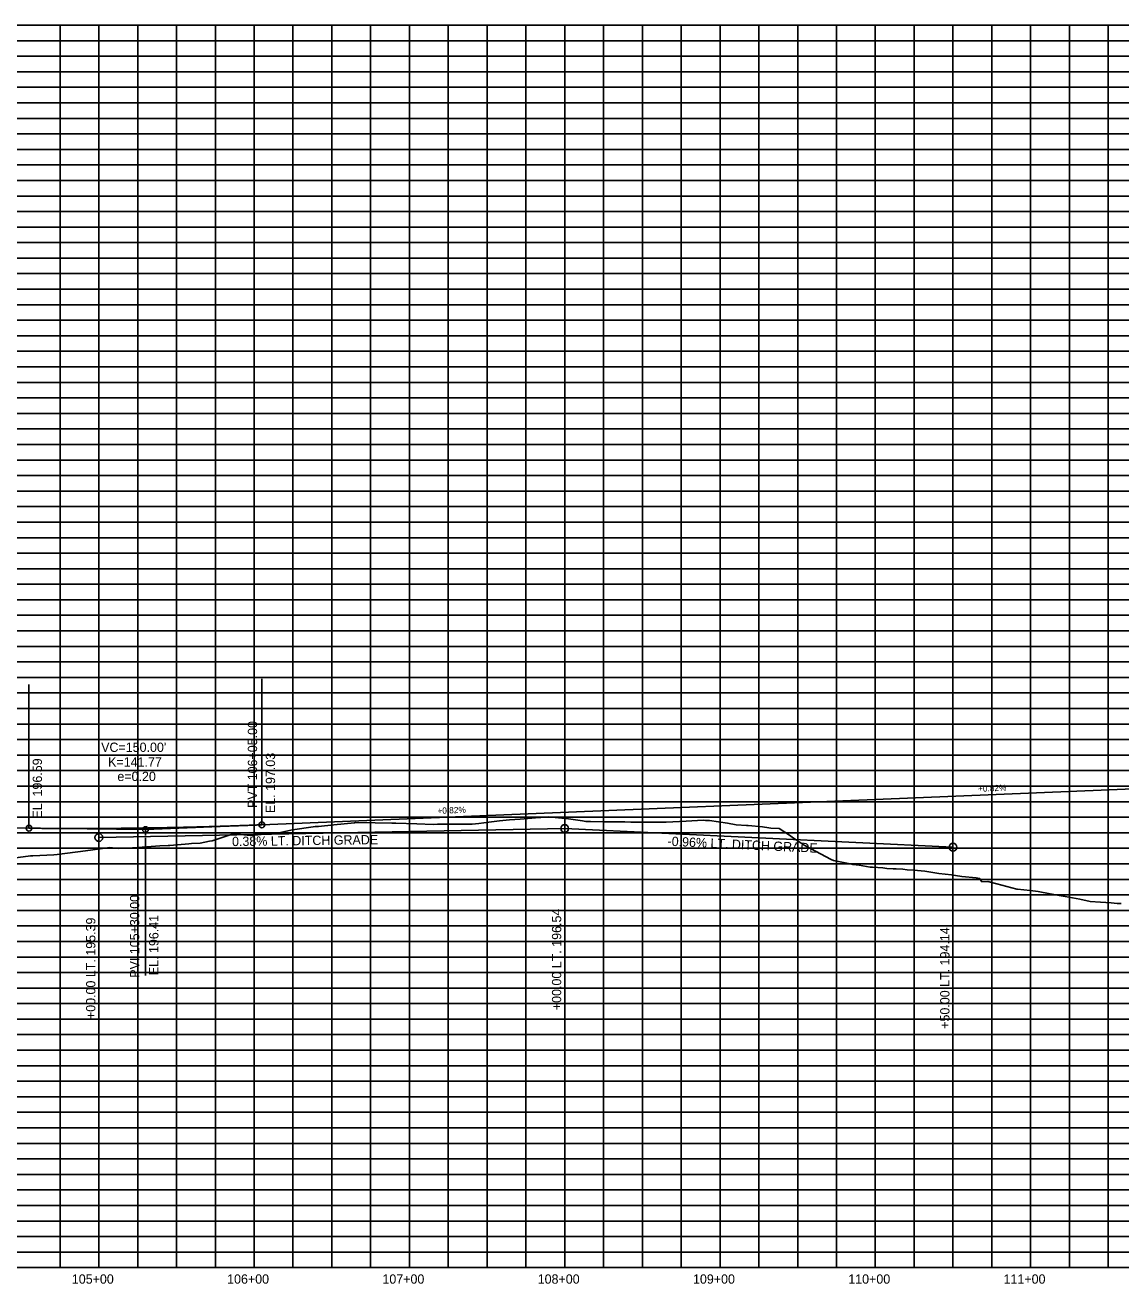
# Model space of a CAD drawing. Extents: x 1384498 to 1391279, y 1965973 to 1976560.
# Drawn here: x 1388901 to 1389607, y 1975299 to 1976110 of the extents above; entities that cross this region are included whole.
import ezdxf

# ---------------------------------------------------------------- set-up
doc = ezdxf.new("R2010")
doc.units = 0
for name, color, linetype in [('Default', 7, 'Continuous'), ('R_Axis_Annotation', 7, 'Continuous'), ('R_Exist Surface', 7, 'Continuous'), ('R_Grid', 7, 'Continuous'), ('R_Grid_Minor', 7, 'Continuous'), ('R_Vert Alg', 7, 'Continuous'), ('R_Vert Alg Annot', 7, 'Continuous')]:
    doc.layers.add(name, color=color, linetype=linetype)

msp = doc.modelspace()

# ---------------------------------------------------------------- linework, layer by layer
at = {"layer": 'Default'}
msp.add_line((1388248.79, 1975309.84), (1390648.79, 1975309.84), dxfattribs=at)
at = {"layer": 'R_Exist Surface'}
for points in [[(1388955.91, 1975580.31), (1388961.26, 1975579.63), (1388970.41, 1975580.09), (1388979.6, 1975580.85), (1388987.97, 1975581.33), (1388993.32, 1975581.64), (1388994.43, 1975581.7), (1389006.66, 1975582.79), (1389008.42, 1975582.92), (1389014, 1975583.18), (1389020, 1975584.4), (1389021.8, 1975584.74), (1389033.35, 1975588.48), (1389035.45, 1975589.12), (1389039.97, 1975588.7), (1389046.35, 1975588.11), (1389046.69, 1975588.15), (1389060.03, 1975589.34), (1389062.84, 1975589.5), (1389064.17, 1975589.74), (1389064.69, 1975589.83), (1389072.45, 1975591.51), (1389073.38, 1975591.65), (1389086.72, 1975593.6), (1389088.08, 1975593.8), (1389089.06, 1975593.83), (1389090.22, 1975593.89), (1389100.06, 1975594.93), (1389113.41, 1975596.34), (1389114.06, 1975596.41), (1389126.75, 1975596.22), (1389137.41, 1975596.06), (1389139.07, 1975596.04), (1389139.19, 1975596.04), (1389140.1, 1975596.01), (1389153.44, 1975595.55), (1389164.11, 1975595.21), (1389166.78, 1975595.28), (1389168.8, 1975595.33), (1389180.13, 1975595.35), (1389189.2, 1975595.39), (1389193.47, 1975595.9), (1389199.97, 1975596.7), (1389206.81, 1975597.43), (1389213.31, 1975598.15), (1389220.16, 1975598.64), (1389232.59, 1975599.57), (1389233.5, 1975599.67), (1389238.35, 1975600.18), (1389246.84, 1975599.25), (1389251.31, 1975598.78), (1389260.19, 1975597.47), (1389262.31, 1975597.15), (1389263.71, 1975597.08), (1389265.3, 1975597), (1389273.53, 1975596.98), (1389286.87, 1975596.91), (1389287.54, 1975596.9), (1389291.37, 1975596.67), (1389299.23, 1975596.61), (1389300.22, 1975596.62), (1389313.56, 1975596.63), (1389314, 1975596.63), (1389326.9, 1975597.32), (1389337.84, 1975597.87), (1389339.51, 1975597.8), (1389340.23, 1975597.83), (1389340.25, 1975597.83), (1389342.11, 1975597.71), (1389353.59, 1975595.94), (1389359.13, 1975595.03), (1389365.77, 1975594.57), (1389366.93, 1975594.47), (1389376.09, 1975593.6), (1389380.28, 1975592.99), (1389381.52, 1975592.81), (1389386.93, 1975592.54), (1389393.62, 1975588.2), (1389395.26, 1975587.07), (1389402.99, 1975581.76), (1389406.96, 1975579.8), (1389420.31, 1975572.73), (1389421.79, 1975571.89), (1389422.77, 1975571.78), (1389423.04, 1975571.74), (1389433.65, 1975569.59), (1389434.38, 1975569.43), (1389438.49, 1975569.04), (1389445.51, 1975567.77), (1389446.99, 1975567.68), (1389453.57, 1975567.23), (1389456.16, 1975566.83), (1389460.34, 1975566.71), (1389462.13, 1975566.65), (1389466.48, 1975566.37), (1389469.32, 1975566.05), (1389473.68, 1975565.68), (1389480.68, 1975565.05), (1389487.02, 1975564.08), (1389489.75, 1975563.65), (1389497.8, 1975562.76)], [(1388893.7, 1975573.41), (1388904.83, 1975574.88), (1388906.11, 1975574.95), (1388906.32, 1975574.96), (1388919.68, 1975575.65), (1388921.92, 1975575.74), (1388940.08, 1975578.19), (1388955.91, 1975580.31)], [(1389497.8, 1975562.76), (1389500.37, 1975562.37), (1389504.45, 1975561.73), (1389513.71, 1975560.72), (1389515.94, 1975560.47), (1389517.48, 1975558.19), (1389521.14, 1975558.41), (1389527.05, 1975556.89), (1389539.94, 1975553.56), (1389540.4, 1975553.52), (1389548.58, 1975552.65), (1389553.74, 1975551.94), (1389555.79, 1975551.65), (1389567.08, 1975549.54), (1389571.11, 1975548.76), (1389580.43, 1975546.98), (1389587.19, 1975545.65), (1389593.77, 1975545.16), (1389600.66, 1975544.63), (1389604.55, 1975544.36), (1389607.11, 1975544.19)]]:
    msp.add_lwpolyline(points, dxfattribs=at)
at = {"layer": 'R_Grid'}
for p, q in [((1388248.79, 1976109.84), (1391048.79, 1976109.84)), ((1388248.79, 1976109.84), (1391048.79, 1976109.84)), ((1388948.79, 1975309.84), (1388948.79, 1976109.84)), ((1389048.79, 1975309.84), (1389048.79, 1976109.84)), ((1389148.79, 1975309.84), (1389148.79, 1976109.84)), ((1389248.79, 1975309.84), (1389248.79, 1976109.84)), ((1389348.79, 1975309.84), (1389348.79, 1976109.84)), ((1389448.79, 1975309.84), (1389448.79, 1976109.84)), ((1389548.79, 1975309.84), (1389548.79, 1976109.84)), ((1388248.79, 1976059.84), (1391048.79, 1976059.84)), ((1388248.79, 1976009.84), (1391048.79, 1976009.84)), ((1388248.79, 1975959.84), (1391048.79, 1975959.84)), ((1388248.79, 1975909.84), (1391048.79, 1975909.84)), ((1388248.79, 1975859.84), (1391048.79, 1975859.84)), ((1388248.79, 1975809.84), (1391048.79, 1975809.84)), ((1388248.79, 1975759.84), (1391048.79, 1975759.84)), ((1388248.79, 1975709.84), (1391048.79, 1975709.84)), ((1388248.79, 1975659.84), (1391048.79, 1975659.84)), ((1388248.79, 1975609.84), (1391048.79, 1975609.84)), ((1388248.79, 1975559.84), (1391048.79, 1975559.84)), ((1388248.79, 1975509.84), (1391048.79, 1975509.84)), ((1388248.79, 1975459.84), (1391048.79, 1975459.84)), ((1388248.79, 1975409.84), (1391048.79, 1975409.84)), ((1388248.79, 1975359.84), (1391048.79, 1975359.84)), ((1388248.79, 1975309.84), (1391048.79, 1975309.84))]:
    msp.add_line(p, q, dxfattribs=at)
at = {"layer": 'R_Grid_Minor'}
for p, q in [((1388923.79, 1975309.84), (1388923.79, 1976109.84)), ((1388973.79, 1975309.84), (1388973.79, 1976109.84)), ((1388998.79, 1975309.84), (1388998.79, 1976109.84)), ((1389023.79, 1975309.84), (1389023.79, 1976109.84)), ((1389073.79, 1975309.84), (1389073.79, 1976109.84)), ((1389098.79, 1975309.84), (1389098.79, 1976109.84)), ((1389123.79, 1975309.84), (1389123.79, 1976109.84)), ((1389173.79, 1975309.84), (1389173.79, 1976109.84)), ((1389198.79, 1975309.84), (1389198.79, 1976109.84)), ((1389223.79, 1975309.84), (1389223.79, 1976109.84)), ((1389273.79, 1975309.84), (1389273.79, 1976109.84)), ((1389298.79, 1975309.84), (1389298.79, 1976109.84)), ((1389323.79, 1975309.84), (1389323.79, 1976109.84)), ((1389373.79, 1975309.84), (1389373.79, 1976109.84)), ((1389398.79, 1975309.84), (1389398.79, 1976109.84)), ((1389423.79, 1975309.84), (1389423.79, 1976109.84)), ((1389473.79, 1975309.84), (1389473.79, 1976109.84)), ((1389498.79, 1975309.84), (1389498.79, 1976109.84)), ((1389523.79, 1975309.84), (1389523.79, 1976109.84)), ((1389573.79, 1975309.84), (1389573.79, 1976109.84)), ((1389598.79, 1975309.84), (1389598.79, 1976109.84)), ((1388248.79, 1976099.84), (1391048.79, 1976099.84)), ((1388248.79, 1976089.84), (1391048.79, 1976089.84)), ((1388248.79, 1976079.84), (1391048.79, 1976079.84)), ((1388248.79, 1976069.84), (1391048.79, 1976069.84)), ((1388248.79, 1976049.84), (1391048.79, 1976049.84)), ((1388248.79, 1976039.84), (1391048.79, 1976039.84)), ((1388248.79, 1976029.84), (1391048.79, 1976029.84)), ((1388248.79, 1976019.84), (1391048.79, 1976019.84)), ((1388248.79, 1975999.84), (1391048.79, 1975999.84)), ((1388248.79, 1975989.84), (1391048.79, 1975989.84)), ((1388248.79, 1975979.84), (1391048.79, 1975979.84)), ((1388248.79, 1975969.84), (1391048.79, 1975969.84)), ((1388248.79, 1975949.84), (1391048.79, 1975949.84)), ((1388248.79, 1975939.84), (1391048.79, 1975939.84)), ((1388248.79, 1975929.84), (1391048.79, 1975929.84)), ((1388248.79, 1975919.84), (1391048.79, 1975919.84)), ((1388248.79, 1975899.84), (1391048.79, 1975899.84)), ((1388248.79, 1975889.84), (1391048.79, 1975889.84)), ((1388248.79, 1975879.84), (1391048.79, 1975879.84)), ((1388248.79, 1975869.84), (1391048.79, 1975869.84)), ((1388248.79, 1975849.84), (1391048.79, 1975849.84)), ((1388248.79, 1975839.84), (1391048.79, 1975839.84)), ((1388248.79, 1975829.84), (1391048.79, 1975829.84)), ((1388248.79, 1975819.84), (1391048.79, 1975819.84)), ((1388248.79, 1975799.84), (1391048.79, 1975799.84)), ((1388248.79, 1975789.84), (1391048.79, 1975789.84)), ((1388248.79, 1975779.84), (1391048.79, 1975779.84)), ((1388248.79, 1975769.84), (1391048.79, 1975769.84)), ((1388248.79, 1975749.84), (1391048.79, 1975749.84)), ((1388248.79, 1975739.84), (1391048.79, 1975739.84)), ((1388248.79, 1975729.84), (1391048.79, 1975729.84)), ((1388248.79, 1975719.84), (1391048.79, 1975719.84)), ((1388248.79, 1975699.84), (1391048.79, 1975699.84)), ((1388248.79, 1975689.84), (1391048.79, 1975689.84)), ((1388248.79, 1975679.84), (1391048.79, 1975679.84)), ((1388248.79, 1975669.84), (1391048.79, 1975669.84)), ((1388248.79, 1975649.84), (1391048.79, 1975649.84)), ((1388248.79, 1975639.84), (1391048.79, 1975639.84)), ((1388248.79, 1975629.84), (1391048.79, 1975629.84)), ((1388248.79, 1975619.84), (1391048.79, 1975619.84)), ((1388248.79, 1975599.84), (1391048.79, 1975599.84)), ((1388248.79, 1975589.84), (1391048.79, 1975589.84)), ((1388248.79, 1975579.84), (1391048.79, 1975579.84)), ((1388248.79, 1975569.84), (1391048.79, 1975569.84)), ((1388248.79, 1975549.84), (1391048.79, 1975549.84)), ((1388248.79, 1975539.84), (1391048.79, 1975539.84)), ((1388248.79, 1975529.84), (1391048.79, 1975529.84)), ((1388248.79, 1975519.84), (1391048.79, 1975519.84)), ((1388248.79, 1975499.84), (1391048.79, 1975499.84)), ((1388248.79, 1975489.84), (1391048.79, 1975489.84)), ((1388248.79, 1975479.84), (1391048.79, 1975479.84)), ((1388248.79, 1975469.84), (1391048.79, 1975469.84)), ((1388248.79, 1975449.84), (1391048.79, 1975449.84)), ((1388248.79, 1975439.84), (1391048.79, 1975439.84)), ((1388248.79, 1975429.84), (1391048.79, 1975429.84)), ((1388248.79, 1975419.84), (1391048.79, 1975419.84)), ((1388248.79, 1975399.84), (1391048.79, 1975399.84)), ((1388248.79, 1975389.84), (1391048.79, 1975389.84)), ((1388248.79, 1975379.84), (1391048.79, 1975379.84)), ((1388248.79, 1975369.84), (1391048.79, 1975369.84)), ((1388248.79, 1975349.84), (1391048.79, 1975349.84)), ((1388248.79, 1975339.84), (1391048.79, 1975339.84)), ((1388248.79, 1975329.84), (1391048.79, 1975329.84)), ((1388248.79, 1975319.84), (1391048.79, 1975319.84))]:
    msp.add_line(p, q, dxfattribs=at)
at = {"layer": 'R_Vert Alg'}
for p, q in [((1389053.79, 1975594.97), (1389634.53, 1975618.83)), ((1388748.79, 1975594.61), (1388903.79, 1975592.77)), ((1389248.79, 1975592.54), (1388948.79, 1975586.79)), ((1389248.79, 1975592.54), (1389498.79, 1975580.54))]:
    msp.add_line(p, q, dxfattribs=at)
msp.add_spline([(1388903.79, 1975592.77), (1388906.79, 1975592.74), (1388909.79, 1975592.71), (1388912.79, 1975592.68), (1388915.79, 1975592.66), (1388918.79, 1975592.64), (1388921.79, 1975592.62), (1388924.79, 1975592.6), (1388927.79, 1975592.59), (1388930.79, 1975592.58), (1388933.79, 1975592.58), (1388936.79, 1975592.58), (1388939.79, 1975592.58), (1388942.79, 1975592.58), (1388945.79, 1975592.59), (1388948.79, 1975592.6), (1388951.79, 1975592.61), (1388954.79, 1975592.63), (1388957.79, 1975592.65), (1388960.79, 1975592.67), (1388963.79, 1975592.7), (1388966.79, 1975592.73), (1388969.79, 1975592.76), (1388972.79, 1975592.8), (1388975.79, 1975592.84), (1388978.79, 1975592.88), (1388981.79, 1975592.93), (1388984.79, 1975592.97), (1388987.79, 1975593.03), (1388990.79, 1975593.08), (1388993.79, 1975593.14), (1388996.79, 1975593.2), (1388999.79, 1975593.27), (1389002.79, 1975593.33), (1389005.79, 1975593.4), (1389008.79, 1975593.48), (1389011.79, 1975593.56), (1389014.79, 1975593.64), (1389017.79, 1975593.72), (1389020.79, 1975593.81), (1389023.79, 1975593.9), (1389026.79, 1975593.99), (1389029.79, 1975594.09), (1389032.79, 1975594.18), (1389035.79, 1975594.29), (1389038.79, 1975594.39), (1389041.79, 1975594.5), (1389044.79, 1975594.61), (1389047.79, 1975594.73), (1389050.79, 1975594.85), (1389053.79, 1975594.97)], degree=3, dxfattribs=at)
at = {"layer": 'R_Vert Alg Annot'}
for p, q in [((1389053.78, 1975604.97), (1389053.78, 1975688.97)), ((1388903.78, 1975601.33), (1388903.78, 1975685.33)), ((1388903.79, 1975592.77), (1388903.79, 1975602.77)), ((1389053.78, 1975594.97), (1389053.78, 1975604.97)), ((1388903.79, 1975592.77), (1388978.78, 1975591.89)), ((1389053.78, 1975594.97), (1388978.78, 1975591.89)), ((1388978.78, 1975591.89), (1388978.78, 1975588.18)), ((1389248.79, 1975592.54), (1389248.79, 1975472.62)), ((1388948.79, 1975586.79), (1388948.79, 1975466.87)), ((1388978.78, 1975586.54), (1388978.78, 1975497.89)), ((1389498.79, 1975580.54), (1389498.79, 1975460.62))]:
    msp.add_line(p, q, dxfattribs=at)
for centre, radius in [((1388903.79, 1975592.77), 1.85), ((1388978.78, 1975591.89), 1.85), ((1389053.78, 1975594.97), 1.85), ((1389248.79, 1975592.54), 2.5), ((1388948.79, 1975586.79), 2.5), ((1389498.79, 1975580.54), 2.5)]:
    msp.add_circle(centre, radius, dxfattribs=at)

# ---------------------------------------------------------------- texts
at = {"layer": 'R_Axis_Annotation'}
for s, p in [('105+00', (1388931.38, 1975299.49)), ('106+00', (1389031.38, 1975299.49)), ('107+00', (1389131.38, 1975299.49)), ('108+00', (1389231.38, 1975299.49)), ('109+00', (1389331.38, 1975299.49)), ('110+00', (1389431.38, 1975299.49)), ('111+00', (1389531.38, 1975299.49))]:
    msp.add_text(s, height=6, dxfattribs=at).set_placement(p)
at = {"layer": 'R_Vert Alg Annot'}
for s, height, rotation, p in [('PVT 106+05.00', 6, 90, (1389050.69, 1975605.79)), (' EL. 197.03', 6, 90, (1389062.26, 1975600.26)), (' EL. 196.59', 6, 90, (1388912.16, 1975596.7)), ('+0.82%', 4, 2.35267, (1389514.99, 1975616.16)), ('+0.82%', 4, 2.35267, (1389166.89, 1975601.97)), ('0.38% LT. DITCH GRADE', 6, 0.74925, (1389034.57, 1975581.24)), ('-0.96% LT. DITCH GRADE', 6, 357.30568, (1389314.89, 1975581.5)), ('PVI 105+30.00', 6, 90, (1388974.82, 1975496.5)), ('+00.00 LT. 195.39', 6, 90, (1388946.54, 1975469.87)), ('EL. 196.41', 6, 90, (1388987.14, 1975498.12)), ('+00.00 LT. 196.54', 6, 90, (1389246.54, 1975475.62)), ('+50.00 LT. 194.14', 6, 90, (1389496.54, 1975463.62))]:
    msp.add_text(s, height=height, rotation=rotation, dxfattribs=at).set_placement(p)
for s, p in [("VC=150.00'", (1388950.26, 1975641.9)), ('K=141.77', (1388954.75, 1975632.41)), ('e=0.20', (1388960.71, 1975623.15))]:
    msp.add_text(s, height=6, dxfattribs=at).set_placement(p)

doc.saveas('drawing.dxf')
